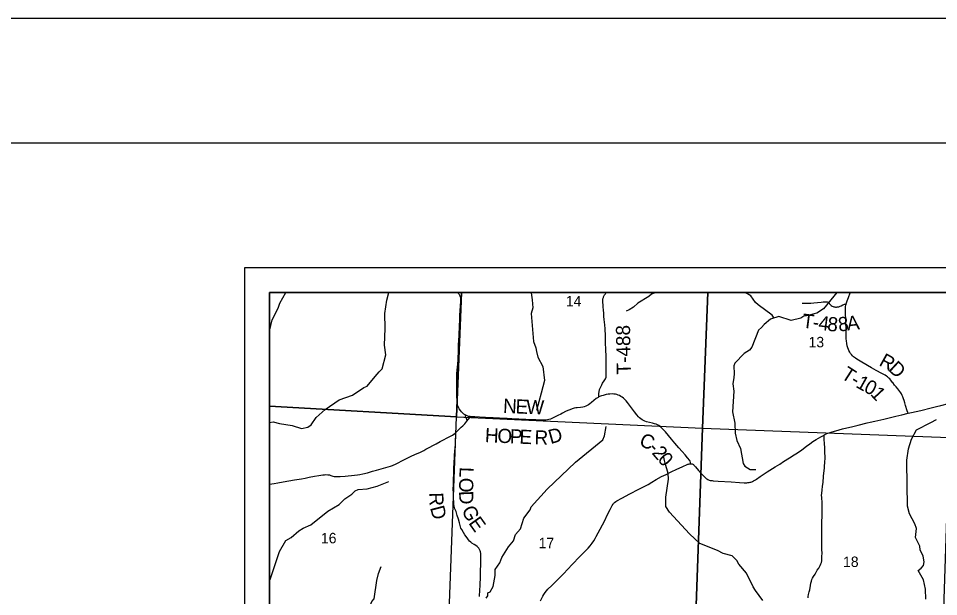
# Model space of a CAD drawing. Extents: x 0 to 34, y 0 to 22.
# Drawn here: x 23.008 to 26.701, y 19.68 to 22 of the extents above; entities that cross this region are included whole.
import ezdxf

# ---------------------------------------------------------------- set-up
doc = ezdxf.new("R2010")
doc.units = 0
for name, color, linetype in [('GM_X_Adjacent_County', 7, 'Continuous'), ('GM_X_County', 7, 'Continuous'), ('GM_X_County_Road', 7, 'Continuous'), ('GM_X_County_Road_Text', 7, 'Continuous'), ('GM_X_Minor_River', 7, 'Continuous'), ('GM_X_Section', 7, 'Continuous'), ('GM_X_Section_Text', 7, 'Continuous'), ('GM_X_Township', 7, 'Continuous'), ('GM_X_Township_Road', 7, 'Continuous'), ('GM_X_Township_Road_Text', 7, 'Continuous'), ('SH_Border', 7, 'Continuous'), ('SH_Cut_Line', 7, 'Continuous'), ('SH_Data', 7, 'Continuous')]:
    doc.layers.add(name, color=color, linetype=linetype)

msp = doc.modelspace()

# ---------------------------------------------------------------- linework, layer by layer
at = {"layer": 'GM_X_Adjacent_County'}
msp.add_lwpolyline([(28.7526, 20.9), (24.0167, 20.9), (24.0167, 14.1), (28.5181, 14.1)], dxfattribs=at)
at = {"layer": 'GM_X_County'}
msp.add_lwpolyline([(28.7526, 20.9), (24.0167, 20.9), (24.0167, 14.1), (28.5181, 14.1)], dxfattribs=at)
at = {"layer": 'GM_X_County_Road'}
for points in [[(24.8021, 20.408), (24.8007, 20.4088), (24.7956, 20.4124), (24.7909, 20.4166), (24.7866, 20.4211), (24.7826, 20.426), (24.7772, 20.4338), (24.7756, 20.4365), (24.7728, 20.4421), (24.7708, 20.4481), (24.7701, 20.4511), (24.7692, 20.4573), (24.7687, 20.4667), (24.7685, 20.4821), (24.7682, 20.4976), (24.768, 20.5101), (24.7679, 20.5256), (24.7681, 20.5536), (24.7685, 20.5753), (24.7692, 20.5878), (24.7715, 20.6125), (24.7726, 20.6311), (24.774, 20.6684), (24.7752, 20.6901), (24.7767, 20.7274), (24.7785, 20.7677), (24.7796, 20.7894), (24.7805, 20.808), (24.7817, 20.8297), (24.7828, 20.8451), (24.784, 20.8668), (24.784, 20.8729), (24.7834, 20.879), (24.7827, 20.8819), (24.7818, 20.8848), (24.7806, 20.8875), (24.7791, 20.8901), (24.7773, 20.8925), (24.7753, 20.8947), (24.773, 20.8968), (24.7706, 20.8986), (24.7684, 20.9)], [(25.3381, 20.4809), (25.3354, 20.4792), (25.3322, 20.4772), (25.3276, 20.4741), (25.3179, 20.4665), (25.3086, 20.4587), (25.3013, 20.4529), (25.2961, 20.4493), (25.2908, 20.446), (25.2851, 20.4432), (25.2791, 20.4412), (25.273, 20.4398), (25.2637, 20.4386), (25.2514, 20.4373), (25.2456, 20.4368), (25.2388, 20.4355), (25.2303, 20.4331), (25.2214, 20.4297), (25.2131, 20.4259), (25.2042, 20.4219), (25.1917, 20.4158), (25.1849, 20.4123), (25.1739, 20.4068), (25.1577, 20.3984), (25.1492, 20.3944), (25.1436, 20.3922), (25.1377, 20.3901), (25.1314, 20.3887), (25.125, 20.388), (25.1186, 20.3879), (25.1094, 20.3879), (25.0938, 20.3883), (25.0845, 20.3888), (25.0721, 20.3896), (25.0445, 20.3905), (25.0166, 20.3915), (24.9887, 20.3927), (24.97, 20.3937), (24.9545, 20.3945), (24.9391, 20.3952), (24.9143, 20.3964), (24.8834, 20.398), (24.8741, 20.3985), (24.8586, 20.3994), (24.84, 20.4005), (24.8276, 20.4012), (24.8226, 20.4017)], [(25.7068, 20.2129), (25.7062, 20.218), (25.7045, 20.2231), (25.703, 20.2256), (25.694, 20.2362), (25.6838, 20.248), (25.6717, 20.2622), (25.6594, 20.2763), (25.6432, 20.2952), (25.6291, 20.3118), (25.605, 20.3404), (25.599, 20.3474), (25.5926, 20.3542), (25.5881, 20.3584), (25.5834, 20.3624), (25.5783, 20.3659), (25.573, 20.369), (25.5674, 20.3715), (25.5616, 20.3736), (25.5527, 20.376), (25.5406, 20.3787), (25.5285, 20.3816), (25.5225, 20.3834), (25.5166, 20.3858), (25.5111, 20.3888), (25.506, 20.3925), (25.5013, 20.3967), (25.4969, 20.4013), (25.4908, 20.4085), (25.4814, 20.4209), (25.461, 20.4485), (25.4533, 20.4582), (25.4473, 20.4654), (25.4411, 20.4719), (25.4367, 20.4761), (25.4319, 20.4798), (25.4265, 20.4833), (25.4214, 20.4861), (25.4158, 20.4883), (25.4103, 20.4901), (25.4041, 20.4915), (25.3975, 20.4925), (25.3907, 20.4928), (25.3825, 20.4926), (25.3752, 20.4918), (25.3669, 20.4903), (25.3554, 20.4873), (25.349, 20.4853), (25.3448, 20.4836), (25.3381, 20.4809)], [(26.5789, 20.4155), (26.5932, 20.4188), (26.6296, 20.4271), (26.6717, 20.4376), (26.6929, 20.4428), (26.711, 20.4472), (26.7411, 20.4544), (26.7593, 20.4586), (26.8229, 20.4731), (26.8471, 20.4786), (26.8546, 20.4804)], [(24.8226, 20.4017), (24.8214, 20.4018), (24.8152, 20.403), (24.8092, 20.4047), (24.8035, 20.4073), (24.8021, 20.408)], [(26.2401, 20.3268), (26.245, 20.3295), (26.2533, 20.3335), (26.2619, 20.337), (26.2736, 20.3411), (26.2884, 20.3454), (26.3155, 20.3523), (26.3578, 20.3627), (26.3788, 20.368), (26.415, 20.3769), (26.427, 20.3797), (26.4452, 20.3838), (26.4815, 20.3923), (26.5026, 20.3973), (26.5297, 20.4039), (26.5539, 20.4097), (26.5789, 20.4155)], [(25.7068, 20.2129), (25.7087, 20.2128), (25.7118, 20.2122), (25.7148, 20.2109), (25.7174, 20.2091), (25.7194, 20.207), (25.7252, 20.2001), (25.7379, 20.1853), (25.7489, 20.1731), (25.7662, 20.1562), (25.7692, 20.1538), (25.7719, 20.1517), (25.7752, 20.1498), (25.7781, 20.1483), (25.7809, 20.1472), (25.785, 20.1462), (25.7886, 20.1456), (25.7925, 20.1451), (25.797, 20.1445), (25.8169, 20.1432), (25.8687, 20.1397), (25.9017, 20.1374), (25.9205, 20.1363), (25.9286, 20.1363), (25.9317, 20.1364), (25.9363, 20.1369), (25.9407, 20.1377), (25.9447, 20.1386), (25.9478, 20.1395), (25.9517, 20.1408), (25.955, 20.1421), (25.9579, 20.1437), (25.9607, 20.1451), (25.9639, 20.147), (25.967, 20.1488), (25.9704, 20.1511), (25.9854, 20.1613), (26.0139, 20.1801), (26.0454, 20.2), (26.0638, 20.2116), (26.0795, 20.2215), (26.103, 20.2364), (26.1222, 20.2484), (26.1352, 20.257), (26.1446, 20.2632), (26.1511, 20.2678), (26.1594, 20.274), (26.1716, 20.2838), (26.184, 20.2929), (26.1968, 20.3016), (26.2099, 20.3097), (26.2287, 20.3206), (26.2401, 20.3268)], [(25.1033, 19.6631), (25.1127, 19.6813), (25.1168, 19.6882), (25.1219, 19.6955), (25.1273, 19.7023), (25.1335, 19.709), (25.1486, 19.7241), (25.1955, 19.7716), (25.2312, 19.8085), (25.2622, 19.8401), (25.2821, 19.8606), (25.2945, 19.8735), (25.3032, 19.8838), (25.3115, 19.894), (25.3177, 19.9034), (25.323, 19.9127), (25.3277, 19.9202), (25.3436, 19.9501), (25.3614, 19.9846), (25.3718, 20.0064), (25.3828, 20.0287), (25.3884, 20.0398), (25.3914, 20.0451), (25.3947, 20.0502), (25.3966, 20.0526), (25.4008, 20.0569), (25.4055, 20.0608), (25.4106, 20.0641), (25.4305, 20.0747), (25.4628, 20.0922), (25.4981, 20.1108), (25.5195, 20.1214), (25.5359, 20.1297), (25.5507, 20.1383), (25.5683, 20.1489), (25.5896, 20.161), (25.6074, 20.1702), (25.6276, 20.1801), (25.6514, 20.191), (25.6717, 20.2003), (25.6955, 20.2109), (25.6976, 20.2117), (25.7001, 20.2124), (25.703, 20.2128), (25.7057, 20.2129), (25.7068, 20.2129)]]:
    msp.add_lwpolyline(points, dxfattribs=at)
at = {"layer": 'GM_X_Minor_River'}
for points in [[(24.0167, 20.7442), (24.0262, 20.7904), (24.051, 20.8368), (24.0573, 20.8573), (24.0812, 20.9)], [(24.0167, 20.3788), (24.0312, 20.3815), (24.0566, 20.3737), (24.1071, 20.3664), (24.1443, 20.3549), (24.1704, 20.3599), (24.1828, 20.3687), (24.2027, 20.3981), (24.2401, 20.4305), (24.2959, 20.4688), (24.3489, 20.4881), (24.3942, 20.5187), (24.4074, 20.5237), (24.4401, 20.5633), (24.4556, 20.582), (24.468, 20.5935), (24.4832, 20.6497), (24.4777, 20.688), (24.4804, 20.7559), (24.4796, 20.8162), (24.4865, 20.8686), (24.495, 20.9)], [(25.067, 20.9), (25.0669, 20.8981), (25.0701, 20.8705), (25.0733, 20.8379), (25.0658, 20.8158), (25.0759, 20.7036), (25.0844, 20.6782), (25.0883, 20.6638), (25.0926, 20.6403), (25.1136, 20.6025), (25.1193, 20.5464), (25.1063, 20.4963), (25.087, 20.426)], [(25.5778, 20.9), (25.5769, 20.8996), (25.564, 20.8991), (25.5497, 20.8929), (25.5391, 20.8834), (25.4938, 20.8573), (25.4772, 20.8406), (25.4598, 20.8298), (25.4474, 20.8248)], [(26.293, 20.9), (26.2927, 20.8995), (26.24, 20.8351), (26.2132, 20.8175), (26.1712, 20.8062), (26.1606, 20.805), (26.1489, 20.7966), (26.1096, 20.7873), (26.0598, 20.8033), (26.0273, 20.7929), (26.0009, 20.7715), (25.99, 20.7589), (25.9783, 20.7494), (25.9514, 20.6802), (25.942, 20.668), (25.9208, 20.6553), (25.8843, 20.6164), (25.8794, 20.6054), (25.8808, 20.5739), (25.8793, 20.5588), (25.8753, 20.5337), (25.8793, 20.5038), (25.8744, 20.4207), (25.8838, 20.376), (25.8855, 20.3358), (25.8917, 20.3066), (25.9059, 20.2737), (25.9173, 20.2138), (25.9238, 20.2036), (25.9454, 20.1901), (25.9553, 20.1894), (25.9682, 20.1894)], [(26.042, 20.7976), (26.0333, 20.8096), (25.9773, 20.851), (25.9671, 20.8604), (25.9483, 20.8861), (25.9248, 20.9)], [(26.6501, 19.6696), (26.6491, 19.7101), (26.6406, 19.7469), (26.6192, 19.7847), (26.6316, 19.7935), (26.6406, 19.8045), (26.6432, 19.8197), (26.6393, 19.8424), (26.6278, 19.8678), (26.6258, 19.8822), (26.609, 19.9162), (26.6122, 19.9534), (26.606, 19.9723), (26.5853, 20.0113), (26.5772, 20.0427), (26.5743, 20.2176), (26.5742, 20.2278), (26.5801, 20.273), (26.5931, 20.311), (26.6126, 20.3483), (26.6708, 20.3789), (26.6927, 20.3901)], [(24.8858, 19.6731), (24.8922, 19.6833), (24.8921, 19.6947), (24.902, 19.6993), (24.9136, 19.7195), (24.9224, 19.7639), (24.9219, 19.7878), (24.9407, 19.8149), (24.9486, 19.8365), (24.9748, 19.8795), (24.9956, 19.9028), (25.0034, 19.9294), (25.0237, 19.9519), (25.0371, 19.9941), (25.0616, 20.028), (25.066, 20.0401), (25.13, 20.1114), (25.2439, 20.219), (25.3533, 20.3092), (25.3608, 20.3248), (25.3677, 20.362)], [(25.9965, 19.6635), (25.9663, 19.7047), (25.9575, 19.7194), (25.9307, 19.7731), (25.8991, 19.8094), (25.8922, 19.8245), (25.8735, 19.843), (25.8374, 19.8526), (25.8135, 19.865), (25.7425, 19.8931), (25.7013, 19.9315), (25.622, 20.0183), (25.6071, 20.0413), (25.6065, 20.0789), (25.6175, 20.1506), (25.6162, 20.1734), (25.6043, 20.2154), (25.6012, 20.2253), (25.5984, 20.2389)], [(24.0167, 19.745), (24.0185, 19.748), (24.03, 19.781), (24.0557, 19.8601), (24.082, 19.9042), (24.1024, 19.9165), (24.1337, 19.9432), (24.1511, 19.9543), (24.1821, 19.967), (24.2507, 20.0221), (24.296, 20.0489), (24.3186, 20.0725), (24.3462, 20.0905), (24.3594, 20.1043), (24.3715, 20.1093), (24.4082, 20.1125), (24.4487, 20.1222), (24.4944, 20.1422)], [(24.361, 19.2618), (24.3522, 19.2868), (24.3524, 19.3149), (24.3603, 19.3377), (24.3631, 19.3722), (24.3835, 19.4478), (24.3891, 19.468), (24.39, 19.501), (24.3938, 19.5112), (24.4221, 19.5308), (24.4249, 19.5642), (24.413, 19.588), (24.4144, 19.6088), (24.4257, 19.6355), (24.4218, 19.6464), (24.4274, 19.6594), (24.4368, 19.67), (24.4474, 19.7437), (24.4537, 19.7718), (24.4649, 19.8007)]]:
    msp.add_lwpolyline(points, dxfattribs=at)
at = {"layer": 'GM_X_Section'}
for p, q in [((25.7754, 20.9), (24.7865, 20.9)), ((26.7655, 20.9), (25.7754, 20.9)), ((24.0167, 20.4434), (24.0167, 19.4375))]:
    msp.add_line(p, q, dxfattribs=at)
for points in [[(24.7865, 20.9), (24.0167, 20.9), (24.0167, 20.4434)], [(24.0167, 20.4434), (24.7666, 20.401), (24.7865, 20.9)], [(24.7865, 20.9), (24.7666, 20.401), (25.7533, 20.3558), (25.7754, 20.9)], [(25.7754, 20.9), (25.7533, 20.3558), (26.7437, 20.3179), (26.7655, 20.9)], [(24.0167, 19.4375), (24.7287, 19.4048), (24.7666, 20.401), (24.0167, 20.4434)]]:
    msp.add_lwpolyline(points, dxfattribs=at)
for points in [[(24.7666, 20.401), (25.7533, 20.3558), (25.7174, 19.3453), (24.7287, 19.4048)], [(25.7533, 20.3558), (26.7437, 20.3179), (26.7101, 19.3051), (25.7174, 19.3453)]]:
    msp.add_lwpolyline(points, close=True, dxfattribs=at)
at = {"layer": 'GM_X_Township'}
msp.add_lwpolyline([(28.7526, 20.9), (24.0167, 20.9), (24.0167, 18.4402)], dxfattribs=at)
at = {"layer": 'GM_X_Township_Road'}
for points in [[(25.3381, 20.4809), (25.3376, 20.488), (25.3379, 20.492), (25.338, 20.4951), (25.3388, 20.5012), (25.3409, 20.5103), (25.3443, 20.5191), (25.3469, 20.5246), (25.3496, 20.5297), (25.3529, 20.5355), (25.3597, 20.5452), (25.3623, 20.5499), (25.3641, 20.5535), (25.3653, 20.556), (25.3666, 20.5597), (25.3674, 20.5633), (25.3677, 20.5678), (25.3677, 20.5748), (25.3675, 20.5941), (25.3674, 20.6087), (25.3671, 20.6245), (25.3667, 20.6502), (25.3664, 20.664), (25.366, 20.6743), (25.3651, 20.6958), (25.3647, 20.7081), (25.3644, 20.7176), (25.3642, 20.7276), (25.3641, 20.7329), (25.364, 20.736), (25.3636, 20.7452), (25.3629, 20.7545), (25.3615, 20.7699), (25.3598, 20.7914), (25.3585, 20.8034), (25.3574, 20.8163), (25.3564, 20.8306), (25.3556, 20.8408), (25.3553, 20.8465), (25.3548, 20.8525), (25.3543, 20.8588), (25.3539, 20.8648), (25.354, 20.8704), (25.3544, 20.874), (25.3551, 20.8769), (25.356, 20.8798), (25.3571, 20.8826), (25.3583, 20.8852), (25.3611, 20.8903), (25.3627, 20.8927), (25.3643, 20.8952), (25.3678, 20.9)], [(26.3306, 20.8532), (26.331, 20.8547), (26.335, 20.8665), (26.3396, 20.8793), (26.3464, 20.8982), (26.347, 20.9)], [(26.1536, 20.8573), (26.1695, 20.8571), (26.189, 20.8573), (26.2009, 20.8582), (26.2297, 20.8611), (26.2378, 20.8621), (26.2421, 20.8625), (26.2457, 20.8628), (26.2483, 20.8628), (26.2506, 20.8626), (26.2524, 20.8623), (26.2541, 20.8619), (26.2569, 20.8608), (26.2594, 20.8592), (26.2617, 20.8567), (26.2641, 20.854), (26.2678, 20.8505), (26.2707, 20.8481), (26.2745, 20.8457), (26.2778, 20.8439), (26.2804, 20.843), (26.2845, 20.8422), (26.288, 20.8418), (26.2916, 20.8417), (26.2946, 20.8419), (26.2978, 20.8425), (26.3009, 20.843), (26.3038, 20.8439), (26.3067, 20.8451), (26.3107, 20.8469), (26.3177, 20.8506), (26.3205, 20.8521), (26.3236, 20.853), (26.3267, 20.8531), (26.3306, 20.8532)], [(26.5789, 20.4155), (26.5781, 20.4182), (26.5757, 20.4257), (26.5691, 20.4464), (26.5656, 20.4572), (26.5628, 20.4671), (26.5611, 20.4729), (26.5581, 20.4815), (26.5558, 20.4871), (26.5529, 20.4927), (26.5499, 20.4976), (26.5461, 20.5029), (26.5374, 20.5135), (26.5306, 20.5211), (26.5246, 20.5284), (26.5171, 20.5383), (26.5153, 20.5408), (26.5099, 20.5482), (26.5055, 20.5532), (26.5023, 20.5565), (26.4991, 20.5593), (26.4965, 20.5615), (26.4922, 20.5648), (26.4869, 20.5682), (26.4817, 20.5714), (26.474, 20.5755), (26.4515, 20.5874), (26.4321, 20.5978), (26.4166, 20.607), (26.3863, 20.6245), (26.3737, 20.6324), (26.3678, 20.6362), (26.3639, 20.6389), (26.36, 20.6418), (26.3558, 20.6456), (26.3513, 20.6508), (26.348, 20.6554), (26.3449, 20.6607), (26.3418, 20.6666), (26.3396, 20.6717), (26.3375, 20.6774), (26.3347, 20.6863), (26.3328, 20.6958), (26.3312, 20.7057), (26.3305, 20.7145), (26.3304, 20.724), (26.3301, 20.7358), (26.33, 20.7451), (26.3301, 20.7587), (26.3295, 20.7758), (26.3291, 20.7875), (26.3288, 20.7934), (26.3276, 20.815), (26.3272, 20.8273), (26.3272, 20.8343), (26.3275, 20.8392), (26.3282, 20.8436), (26.3294, 20.8486), (26.3306, 20.8532)], [(24.8098, 20.3855), (24.8079, 20.39), (24.8065, 20.3937), (24.8053, 20.3965), (24.8044, 20.3987), (24.8033, 20.4007), (24.8023, 20.4036), (24.8021, 20.4056), (24.8021, 20.408)], [(24.8098, 20.3855), (24.8121, 20.3885), (24.814, 20.3909), (24.8226, 20.4017)], [(24.7606, 20.3352), (24.7653, 20.3392), (24.7719, 20.3457), (24.7782, 20.3525), (24.7847, 20.3592), (24.7914, 20.3656), (24.8002, 20.3733), (24.8046, 20.3784), (24.8084, 20.3835), (24.8098, 20.3855)], [(24.0167, 20.131), (24.0253, 20.1324), (24.0345, 20.1339), (24.0498, 20.1364), (24.0711, 20.1401), (24.117, 20.1481), (24.1445, 20.1527), (24.1598, 20.1555), (24.1751, 20.1584), (24.1964, 20.1626), (24.2147, 20.1658), (24.23, 20.1682), (24.2362, 20.1688), (24.2427, 20.1693), (24.2508, 20.1687), (24.2563, 20.1677), (24.2618, 20.1659), (24.2664, 20.1644), (24.2703, 20.1631), (24.2751, 20.1621), (24.2801, 20.1617), (24.2903, 20.1617), (24.2991, 20.162), (24.3203, 20.1633), (24.3575, 20.1664), (24.3698, 20.1678), (24.379, 20.1694), (24.3911, 20.1721), (24.4091, 20.1769), (24.43, 20.1828), (24.4449, 20.1871), (24.4927, 20.1999), (24.5015, 20.2026), (24.5102, 20.206), (24.5242, 20.2126), (24.5547, 20.228), (24.5686, 20.2349), (24.5852, 20.2431), (24.5993, 20.2494), (24.622, 20.2592), (24.6303, 20.2633), (24.6358, 20.2663), (24.6439, 20.2708), (24.6602, 20.2796), (24.6711, 20.2855), (24.6847, 20.2929), (24.7011, 20.3018), (24.7423, 20.3236), (24.7504, 20.3281), (24.7557, 20.3315), (24.7606, 20.3352)], [(24.8583, 19.6794), (24.8594, 19.6872), (24.8605, 19.6999), (24.8617, 19.7299), (24.8625, 19.7547), (24.8627, 19.7671), (24.8637, 19.8251), (24.8642, 19.845), (24.8637, 19.8521), (24.8629, 19.8589), (24.8618, 19.8631), (24.8606, 19.866), (24.8593, 19.8689), (24.8578, 19.8717), (24.856, 19.8744), (24.8538, 19.8767), (24.8498, 19.8802), (24.8438, 19.8844), (24.8371, 19.8884), (24.828, 19.8944), (24.8237, 19.8975), (24.8186, 19.9023), (24.8146, 19.9071), (24.8089, 19.9153), (24.8006, 19.9274), (24.7946, 19.937), (24.788, 19.9483), (24.7846, 19.9542), (24.7826, 19.9594), (24.778, 19.976), (24.7745, 19.9904), (24.7697, 20.0056), (24.7647, 20.021), (24.7604, 20.0323), (24.7574, 20.043), (24.7563, 20.049), (24.7555, 20.0578), (24.7546, 20.076), (24.7543, 20.0941), (24.7537, 20.1114), (24.7539, 20.1288), (24.7547, 20.154), (24.7553, 20.1695), (24.7561, 20.188), (24.7578, 20.2219), (24.7584, 20.2343), (24.7592, 20.2467), (24.7601, 20.2622), (24.762, 20.2901), (24.763, 20.3087), (24.7635, 20.3242), (24.7636, 20.327), (24.7633, 20.3291), (24.7628, 20.3307), (24.7624, 20.332), (24.7606, 20.3352)], [(26.1775, 19.6744), (26.1783, 19.6797), (26.1796, 19.6883), (26.1817, 19.6982), (26.184, 19.7072), (26.1872, 19.7239), (26.1888, 19.7331), (26.1907, 19.7414), (26.1931, 19.7482), (26.1958, 19.7541), (26.1991, 19.7598), (26.2058, 19.7703), (26.2147, 19.7857), (26.2207, 19.7942), (26.2237, 19.7996), (26.2265, 19.805), (26.229, 19.8106), (26.2309, 19.8165), (26.2322, 19.8225), (26.233, 19.8286), (26.2333, 19.8378), (26.2335, 19.8564), (26.2334, 19.8657), (26.2328, 19.8873), (26.2325, 19.9027), (26.2324, 19.912), (26.2323, 19.9213), (26.2323, 19.9337), (26.2326, 19.9522), (26.233, 19.9677), (26.2334, 19.9832), (26.2338, 19.9987), (26.2342, 20.0235), (26.2342, 20.042), (26.2336, 20.0606), (26.2327, 20.0729), (26.2322, 20.0791), (26.2321, 20.0853), (26.2325, 20.0946), (26.2339, 20.1069), (26.236, 20.1222), (26.2377, 20.1376), (26.24, 20.1623), (26.2429, 20.1963), (26.244, 20.2056), (26.2449, 20.2147), (26.2455, 20.2234), (26.2457, 20.2306), (26.2457, 20.2385), (26.2452, 20.2606), (26.2449, 20.276), (26.2438, 20.294), (26.2428, 20.3104), (26.2421, 20.3188), (26.2416, 20.3227), (26.241, 20.3248), (26.2401, 20.3268)]]:
    msp.add_lwpolyline(points, dxfattribs=at)
at = {"layer": 'SH_Border'}
msp.add_lwpolyline([(2, 21.5), (33.5, 21.5), (33.5, 0.5), (2, 0.5)], close=True, dxfattribs=at)
at = {"layer": 'SH_Cut_Line'}
msp.add_lwpolyline([(0, 0), (34, 0), (34, 22), (0, 22)], close=True, dxfattribs=at)
at = {"layer": 'SH_Data'}
for points in [[(23.9167, 21), (30.9167, 21), (30.9167, 14), (23.9167, 14)], [(24.0167, 20.9), (30.8167, 20.9), (30.8167, 14.1), (24.0167, 14.1)]]:
    msp.add_lwpolyline(points, close=True, dxfattribs=at)

# ---------------------------------------------------------------- texts
at = {"layer": 'GM_X_County_Road_Text'}
for s, rotation, p in [('N', 357.3179, (24.9526, 20.4173)), ('E', 357.3195, (25.0025, 20.415)), ('W', 358.0243, (25.0457, 20.413)), ('H', 357.3508, (24.8798, 20.2998)), ('O', 357.3541, (24.9298, 20.2975)), ('P', 357.3687, (24.9797, 20.2952)), ('E', 357.4149, (25.0181, 20.2934)), ('D', 15.6783, (25.1442, 20.2915)), ('R', 358.1754, (25.0788, 20.2907)), ('C', 334.9711, (25.4956, 20.2887)), ('-', 310.901, (25.5329, 20.2728)), ('2', 310.7977, (25.5481, 20.2551)), ('0', 310.7718, (25.571, 20.2287))]:
    msp.add_text(s, height=0.0568, rotation=rotation, dxfattribs=at).set_placement(p)
at = {"layer": 'GM_X_Section_Text'}
for s, p in [('14', (25.2056, 20.8445)), ('13', (26.1797, 20.6801)), ('16', (24.2226, 19.8934)), ('17', (25.0964, 19.8739)), ('18', (26.3181, 19.7984))]:
    msp.add_text(s, height=0.04186, rotation=0, dxfattribs=at).set_placement(p)
at = {"layer": 'GM_X_Township_Road_Text'}
for s, height, rotation, p in [('T', 0.0568, 352.7336, (26.1514, 20.7596)), ('4', 0.0568, 352.8889, (26.2169, 20.7512)), ('8', 0.0568, 353.9232, (26.2527, 20.7468)), ('8', 0.0568, 6.498, (26.3011, 20.7431)), ('A', 0.0568, 6.5429, (26.3359, 20.7471)), ('T-488', 0.05682, 91.1187, (25.4667, 20.5716)), ('-', 0.0568, 352.7706, (26.1936, 20.7542)), ('R', 0.0568, 330.8332, (26.4587, 20.6096)), ('D', 0.0568, 317.3164, (26.4966, 20.589)), ('T', 0.0568, 327.2668, (26.3065, 20.5588)), ('-', 0.0568, 329.8629, (26.3446, 20.5344)), ('1', 0.0568, 330.7283, (26.3656, 20.5222)), ('0', 0.0568, 332.1869, (26.3975, 20.5043)), ('1', 0.0568, 312.9241, (26.4245, 20.491)), ('L', 0.0568, 267.8824, (24.7795, 20.2003)), ('O', 0.0568, 268.5343, (24.778, 20.1571)), ('R', 0.0568, 271.4326, (24.6571, 20.0971)), ('D', 0.0568, 272.0721, (24.7767, 20.1033)), ('D', 0.0568, 284.5673, (24.6602, 20.0367)), ('G', 0.0568, 296.9986, (24.7852, 20.0274)), ('E', 0.0568, 305.5671, (24.8127, 19.9749))]:
    msp.add_text(s, height=height, rotation=rotation, dxfattribs=at).set_placement(p)

doc.saveas('drawing.dxf')
